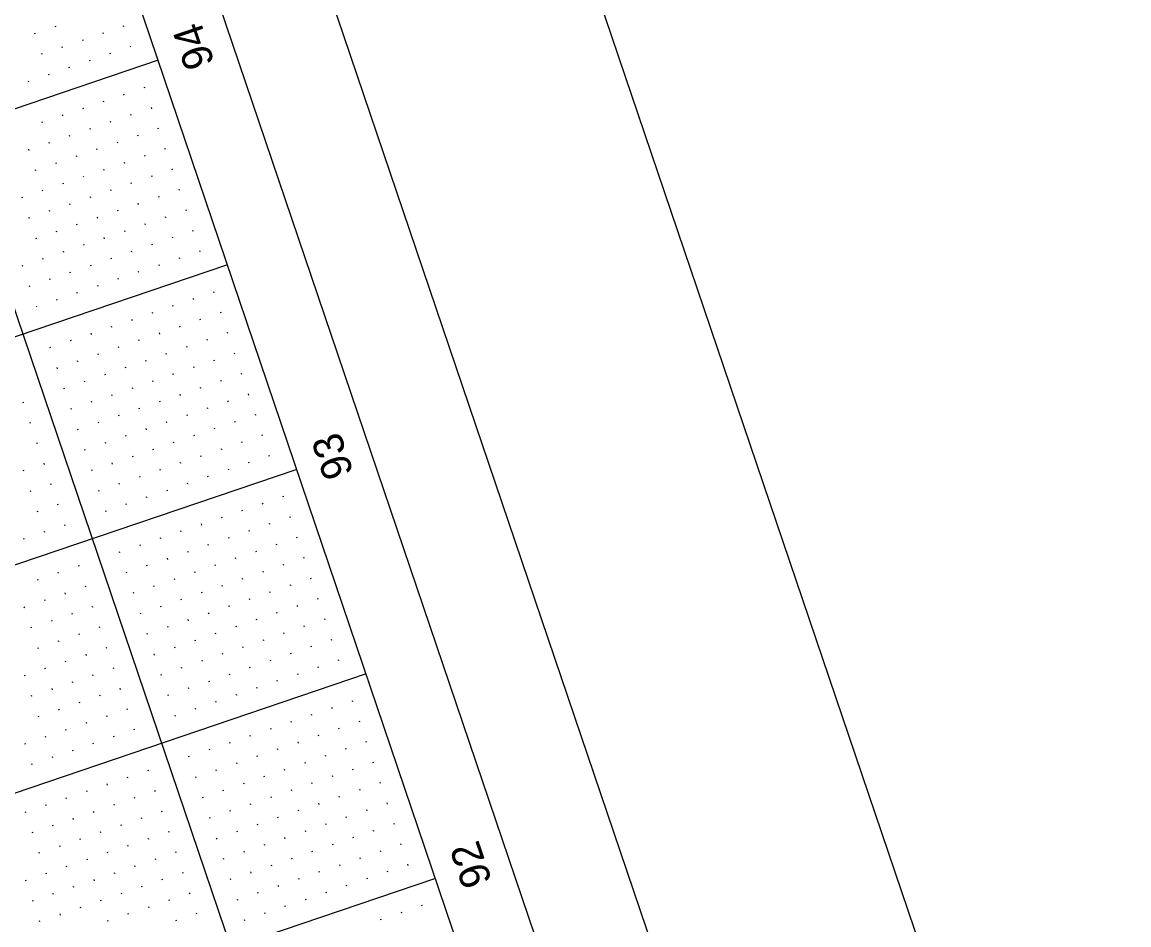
# Model space of a CAD drawing. Extents: x 2150318 to 2152065, y 143281 to 145371.
# Drawn here: x 2151643.3 to 2151899.7, y 144207 to 144416 of the extents above; entities that cross this region are included whole.
import ezdxf

# ---------------------------------------------------------------- set-up
doc = ezdxf.new("R2010")
doc.units = 0
for name, color, linetype in [('SHT_Plan_Profile_Sheet_Sta_Txt', 7, 'Continuous'), ('SHT_Plot_Shape_Full', 7, 'Continuous'), ('SHT_Plot_Shape_Half', 7, 'Continuous'), ('SHT_Profile_Grid_Major', 7, 'Continuous'), ('SHT_Profile_Grid_Minor', 7, 'Continuous'), ('SHT_Sheet_Border', 7, 'Continuous')]:
    doc.layers.add(name, color=color, linetype=linetype)

msp = doc.modelspace()

# ---------------------------------------------------------------- linework, layer by layer
at = {"layer": 'SHT_Plot_Shape_Full'}
msp.add_lwpolyline([(2150896.74, 143280.62), (2150318.46, 144985.2), (2151454.85, 145370.71), (2152033.12, 143666.13)], close=True, dxfattribs=at)
at = {"layer": 'SHT_Plot_Shape_Half'}
msp.add_lwpolyline([(2150909.49, 143371.4), (2150363.35, 144981.29), (2151405.04, 145334.68), (2151951.18, 143724.79)], close=True, dxfattribs=at)
at = {"layer": 'SHT_Profile_Grid_Major'}
for p, q in [((2151832.26, 143787.41), (2151326.27, 145278.92)), ((2151674.81, 144407.18), (2151224.91, 144254.55)), ((2151690.87, 144359.83), (2151240.97, 144207.2)), ((2151706.93, 144312.48), (2151257.04, 144159.85)), ((2151723, 144265.13), (2151273.1, 144112.5)), ((2151739.06, 144217.78), (2151308.18, 144071.6))]:
    msp.add_line(p, q, dxfattribs=at)
at = {"layer": 'SHT_Profile_Grid_Minor'}
for p, q in [((2151646.35, 144413.23), (2151646.27, 144413.47)), ((2151651.09, 144414.84), (2151651.01, 144415.07)), ((2151662.17, 144413.32), (2151662.09, 144413.55)), ((2151666.9, 144414.92), (2151666.82, 144415.16)), ((2151657.43, 144411.71), (2151657.35, 144411.95)), ((2151668.51, 144410.19), (2151668.43, 144410.42)), ((2151647.96, 144408.5), (2151647.88, 144408.73)), ((2151652.7, 144410.1), (2151652.62, 144410.34)), ((2151663.77, 144408.58), (2151663.69, 144408.82)), ((2151654.3, 144405.37), (2151654.22, 144405.6)), ((2151659.04, 144406.97), (2151658.96, 144407.21)), ((2151649.57, 144403.76), (2151649.49, 144404)), ((2151644.83, 144402.16), (2151644.75, 144402.39)), ((2151671.72, 144400.72), (2151671.64, 144400.95)), ((2151662.25, 144397.5), (2151662.17, 144397.74)), ((2151666.98, 144399.11), (2151666.9, 144399.35)), ((2151657.52, 144395.9), (2151657.43, 144396.13)), ((2151673.33, 144395.98), (2151673.25, 144396.22)), ((2151648.05, 144392.69), (2151647.96, 144392.92)), ((2151652.78, 144394.29), (2151652.7, 144394.53)), ((2151663.86, 144392.77), (2151663.78, 144393.01)), ((2151668.59, 144394.38), (2151668.51, 144394.61)), ((2151659.12, 144391.16), (2151659.04, 144391.4)), ((2151670.2, 144389.64), (2151670.12, 144389.88)), ((2151674.93, 144391.25), (2151674.85, 144391.48)), ((2151649.65, 144387.95), (2151649.57, 144388.19)), ((2151654.39, 144389.56), (2151654.31, 144389.79)), ((2151665.46, 144388.03), (2151665.38, 144388.27)), ((2151644.92, 144386.34), (2151644.84, 144386.58)), ((2151655.99, 144384.82), (2151655.91, 144385.06)), ((2151660.73, 144386.43), (2151660.65, 144386.66)), ((2151671.8, 144384.91), (2151671.72, 144385.14)), ((2151676.54, 144386.51), (2151676.46, 144386.75)), ((2151651.26, 144383.22), (2151651.18, 144383.45)), ((2151667.07, 144383.3), (2151666.99, 144383.54)), ((2151646.52, 144381.61), (2151646.44, 144381.85)), ((2151657.6, 144380.09), (2151657.52, 144380.32)), ((2151662.33, 144381.69), (2151662.25, 144381.93)), ((2151673.41, 144380.17), (2151673.33, 144380.41)), ((2151678.15, 144381.78), (2151678.06, 144382.01)), ((2151648.13, 144376.87), (2151648.05, 144377.11)), ((2151652.86, 144378.48), (2151652.78, 144378.72)), ((2151663.94, 144376.96), (2151663.86, 144377.19)), ((2151668.68, 144378.56), (2151668.59, 144378.8)), ((2151679.75, 144377.04), (2151679.67, 144377.28)), ((2151643.39, 144375.27), (2151643.31, 144375.5)), ((2151659.21, 144375.35), (2151659.13, 144375.59)), ((2151675.02, 144375.44), (2151674.94, 144375.67)), ((2151649.74, 144372.14), (2151649.66, 144372.38)), ((2151654.47, 144373.75), (2151654.39, 144373.98)), ((2151665.55, 144372.22), (2151665.47, 144372.46)), ((2151670.28, 144373.83), (2151670.2, 144374.07)), ((2151681.36, 144372.31), (2151681.28, 144372.54)), ((2151645, 144370.53), (2151644.92, 144370.77)), ((2151660.81, 144370.62), (2151660.73, 144370.85)), ((2151671.89, 144369.09), (2151671.81, 144369.33)), ((2151676.62, 144370.7), (2151676.54, 144370.94)), ((2151651.34, 144367.4), (2151651.26, 144367.64)), ((2151656.08, 144369.01), (2151656, 144369.25)), ((2151667.15, 144367.49), (2151667.07, 144367.72)), ((2151682.96, 144367.57), (2151682.88, 144367.81)), ((2151646.61, 144365.8), (2151646.53, 144366.03)), ((2151657.68, 144364.28), (2151657.6, 144364.51)), ((2151662.42, 144365.88), (2151662.34, 144366.12)), ((2151673.49, 144364.36), (2151673.41, 144364.6)), ((2151678.23, 144365.97), (2151678.15, 144366.2)), ((2151652.95, 144362.67), (2151652.87, 144362.91)), ((2151668.76, 144362.75), (2151668.68, 144362.99)), ((2151684.57, 144362.84), (2151684.49, 144363.07)), ((2151643.48, 144359.46), (2151643.4, 144359.69)), ((2151648.21, 144361.06), (2151648.13, 144361.3)), ((2151659.29, 144359.54), (2151659.21, 144359.78)), ((2151664.02, 144361.15), (2151663.94, 144361.38)), ((2151675.1, 144359.62), (2151675.02, 144359.86)), ((2151679.84, 144361.23), (2151679.76, 144361.47)), ((2151649.82, 144356.33), (2151649.74, 144356.56)), ((2151654.55, 144357.93), (2151654.47, 144358.17)), ((2151665.63, 144356.41), (2151665.55, 144356.65)), ((2151670.37, 144358.02), (2151670.29, 144358.26)), ((2151645.08, 144354.72), (2151645, 144354.96)), ((2151660.9, 144354.81), (2151660.82, 144355.04)), ((2151651.43, 144351.59), (2151651.35, 144351.83)), ((2151656.16, 144353.2), (2151656.08, 144353.44)), ((2151683.05, 144351.76), (2151682.97, 144352)), ((2151687.78, 144353.37), (2151687.7, 144353.6)), ((2151646.69, 144349.99), (2151646.61, 144350.22)), ((2151678.31, 144350.15), (2151678.23, 144350.39)), ((2151689.39, 144348.63), (2151689.31, 144348.87)), ((2151668.84, 144346.94), (2151668.76, 144347.18)), ((2151673.58, 144348.55), (2151673.5, 144348.79)), ((2151684.65, 144347.03), (2151684.57, 144347.26)), ((2151659.37, 144343.73), (2151659.29, 144343.97)), ((2151664.11, 144345.34), (2151664.03, 144345.57)), ((2151675.18, 144343.81), (2151675.1, 144344.05)), ((2151679.92, 144345.42), (2151679.84, 144345.66)), ((2151691, 144343.9), (2151690.92, 144344.13)), ((2151654.64, 144342.12), (2151654.56, 144342.36)), ((2151670.45, 144342.21), (2151670.37, 144342.44)), ((2151686.26, 144342.29), (2151686.18, 144342.53)), ((2151649.9, 144340.52), (2151649.82, 144340.75)), ((2151660.98, 144338.99), (2151660.9, 144339.23)), ((2151665.71, 144340.6), (2151665.63, 144340.84)), ((2151676.79, 144339.08), (2151676.71, 144339.32)), ((2151681.53, 144340.68), (2151681.45, 144340.92)), ((2151692.6, 144339.16), (2151692.52, 144339.4)), ((2151651.51, 144335.78), (2151651.43, 144336.02)), ((2151656.24, 144337.39), (2151656.16, 144337.62)), ((2151667.32, 144335.87), (2151667.24, 144336.1)), ((2151672.06, 144337.47), (2151671.98, 144337.71)), ((2151683.13, 144335.95), (2151683.05, 144336.19)), ((2151687.87, 144337.56), (2151687.79, 144337.79)), ((2151662.59, 144334.26), (2151662.51, 144334.5)), ((2151678.4, 144334.34), (2151678.32, 144334.58)), ((2151694.21, 144334.43), (2151694.13, 144334.66)), ((2151653.12, 144331.05), (2151653.04, 144331.28)), ((2151657.85, 144332.65), (2151657.77, 144332.89)), ((2151668.93, 144331.13), (2151668.85, 144331.37)), ((2151673.66, 144332.74), (2151673.58, 144332.97)), ((2151684.74, 144331.21), (2151684.66, 144331.45)), ((2151689.47, 144332.82), (2151689.39, 144333.06)), ((2151664.19, 144329.52), (2151664.11, 144329.76)), ((2151680, 144329.61), (2151679.92, 144329.85)), ((2151691.08, 144328.09), (2151691, 144328.32)), ((2151695.81, 144329.69), (2151695.73, 144329.93)), ((2151643.65, 144327.83), (2151643.57, 144328.07)), ((2151654.72, 144326.31), (2151654.64, 144326.55)), ((2151659.46, 144327.92), (2151659.38, 144328.16)), ((2151670.53, 144326.4), (2151670.45, 144326.63)), ((2151675.27, 144328), (2151675.19, 144328.24)), ((2151686.34, 144326.48), (2151686.26, 144326.72)), ((2151645.25, 144323.1), (2151645.17, 144323.34)), ((2151661.06, 144323.18), (2151660.98, 144323.42)), ((2151665.8, 144324.79), (2151665.72, 144325.03)), ((2151676.87, 144323.27), (2151676.79, 144323.5)), ((2151681.61, 144324.87), (2151681.53, 144325.11)), ((2151692.69, 144323.35), (2151692.61, 144323.59)), ((2151697.42, 144324.96), (2151697.34, 144325.19)), ((2151656.33, 144321.58), (2151656.25, 144321.81)), ((2151672.14, 144321.66), (2151672.06, 144321.9)), ((2151687.95, 144321.75), (2151687.87, 144321.98)), ((2151646.86, 144318.36), (2151646.78, 144318.6)), ((2151662.67, 144318.45), (2151662.59, 144318.69)), ((2151667.4, 144320.05), (2151667.32, 144320.29)), ((2151678.48, 144318.53), (2151678.4, 144318.77)), ((2151683.22, 144320.14), (2151683.14, 144320.38)), ((2151694.29, 144318.62), (2151694.21, 144318.85)), ((2151699.03, 144320.22), (2151698.95, 144320.46)), ((2151657.94, 144316.84), (2151657.85, 144317.08)), ((2151669.01, 144315.32), (2151668.93, 144315.56)), ((2151673.75, 144316.93), (2151673.67, 144317.16)), ((2151684.82, 144315.4), (2151684.74, 144315.64)), ((2151689.56, 144317.01), (2151689.48, 144317.25)), ((2151700.63, 144315.49), (2151700.55, 144315.72)), ((2151648.47, 144313.63), (2151648.38, 144313.87)), ((2151664.28, 144313.71), (2151664.2, 144313.95)), ((2151680.09, 144313.8), (2151680.01, 144314.03)), ((2151695.9, 144313.88), (2151695.82, 144314.12)), ((2151643.73, 144312.02), (2151643.65, 144312.26)), ((2151659.54, 144312.11), (2151659.46, 144312.34)), ((2151670.62, 144310.58), (2151670.54, 144310.82)), ((2151675.35, 144312.19), (2151675.27, 144312.43)), ((2151686.43, 144310.67), (2151686.35, 144310.91)), ((2151691.16, 144312.28), (2151691.08, 144312.51)), ((2151650.07, 144308.89), (2151649.99, 144309.13)), ((2151665.88, 144308.98), (2151665.8, 144309.22)), ((2151681.69, 144309.06), (2151681.61, 144309.3)), ((2151645.34, 144307.29), (2151645.26, 144307.52)), ((2151661.15, 144307.37), (2151661.07, 144307.61)), ((2151672.22, 144305.85), (2151672.14, 144306.09)), ((2151676.96, 144307.46), (2151676.88, 144307.69)), ((2151703.85, 144306.02), (2151703.77, 144306.25)), ((2151646.94, 144302.55), (2151646.86, 144302.79)), ((2151651.68, 144304.16), (2151651.6, 144304.4)), ((2151662.75, 144302.64), (2151662.67, 144302.87)), ((2151667.49, 144304.24), (2151667.41, 144304.48)), ((2151694.38, 144302.81), (2151694.3, 144303.04)), ((2151699.11, 144304.41), (2151699.03, 144304.65)), ((2151689.64, 144301.2), (2151689.56, 144301.44)), ((2151705.45, 144301.28), (2151705.37, 144301.52)), ((2151648.55, 144297.82), (2151648.47, 144298.06)), ((2151653.28, 144299.42), (2151653.2, 144299.66)), ((2151680.17, 144297.99), (2151680.09, 144298.22)), ((2151684.91, 144299.59), (2151684.83, 144299.83)), ((2151695.98, 144298.07), (2151695.9, 144298.31)), ((2151700.72, 144299.68), (2151700.64, 144299.91)), ((2151643.81, 144296.21), (2151643.73, 144296.45)), ((2151670.7, 144294.77), (2151670.62, 144295.01)), ((2151675.44, 144296.38), (2151675.36, 144296.62)), ((2151686.51, 144294.86), (2151686.43, 144295.09)), ((2151691.25, 144296.46), (2151691.17, 144296.7)), ((2151702.32, 144294.94), (2151702.24, 144295.18)), ((2151707.06, 144296.55), (2151706.98, 144296.78)), ((2151665.97, 144293.17), (2151665.89, 144293.4)), ((2151681.78, 144293.25), (2151681.7, 144293.49)), ((2151697.59, 144293.34), (2151697.51, 144293.57)), ((2151656.5, 144289.95), (2151656.42, 144290.19)), ((2151672.31, 144290.04), (2151672.23, 144290.28)), ((2151677.04, 144291.64), (2151676.96, 144291.88)), ((2151688.12, 144290.12), (2151688.04, 144290.36)), ((2151692.85, 144291.73), (2151692.77, 144291.97)), ((2151703.93, 144290.21), (2151703.85, 144290.44)), ((2151708.67, 144291.81), (2151708.58, 144292.05)), ((2151651.76, 144288.35), (2151651.68, 144288.59)), ((2151667.57, 144288.43), (2151667.49, 144288.67)), ((2151683.38, 144288.52), (2151683.3, 144288.75)), ((2151699.2, 144288.6), (2151699.11, 144288.84)), ((2151710.27, 144287.08), (2151710.19, 144287.31)), ((2151647.03, 144286.74), (2151646.95, 144286.98)), ((2151658.1, 144285.22), (2151658.02, 144285.46)), ((2151673.91, 144285.3), (2151673.83, 144285.54)), ((2151678.65, 144286.91), (2151678.57, 144287.15)), ((2151689.73, 144285.39), (2151689.65, 144285.62)), ((2151694.46, 144286.99), (2151694.38, 144287.23)), ((2151705.54, 144285.47), (2151705.46, 144285.71)), ((2151648.63, 144282.01), (2151648.55, 144282.24)), ((2151653.37, 144283.61), (2151653.29, 144283.85)), ((2151669.18, 144283.7), (2151669.1, 144283.93)), ((2151680.26, 144282.18), (2151680.18, 144282.41)), ((2151684.99, 144283.78), (2151684.91, 144284.02)), ((2151696.07, 144282.26), (2151695.99, 144282.5)), ((2151700.8, 144283.87), (2151700.72, 144284.1)), ((2151711.88, 144282.34), (2151711.8, 144282.58)), ((2151643.9, 144280.4), (2151643.82, 144280.64)), ((2151659.71, 144280.48), (2151659.63, 144280.72)), ((2151675.52, 144280.57), (2151675.44, 144280.81)), ((2151691.33, 144280.65), (2151691.25, 144280.89)), ((2151707.14, 144280.74), (2151707.06, 144280.97)), ((2151650.24, 144277.27), (2151650.16, 144277.51)), ((2151654.97, 144278.88), (2151654.89, 144279.12)), ((2151670.79, 144278.96), (2151670.71, 144279.2)), ((2151681.86, 144277.44), (2151681.78, 144277.68)), ((2151686.6, 144279.05), (2151686.52, 144279.28)), ((2151697.67, 144277.52), (2151697.59, 144277.76)), ((2151702.41, 144279.13), (2151702.33, 144279.37)), ((2151713.48, 144277.61), (2151713.4, 144277.84)), ((2151645.5, 144275.67), (2151645.42, 144275.9)), ((2151661.32, 144275.75), (2151661.24, 144275.99)), ((2151677.13, 144275.83), (2151677.05, 144276.07)), ((2151688.2, 144274.31), (2151688.12, 144274.55)), ((2151692.94, 144275.92), (2151692.86, 144276.15)), ((2151704.01, 144274.4), (2151703.93, 144274.63)), ((2151708.75, 144276), (2151708.67, 144276.24)), ((2151651.85, 144272.54), (2151651.77, 144272.77)), ((2151656.58, 144274.14), (2151656.5, 144274.38)), ((2151672.39, 144274.23), (2151672.31, 144274.46)), ((2151683.47, 144272.71), (2151683.39, 144272.94)), ((2151699.28, 144272.79), (2151699.2, 144273.03)), ((2151715.09, 144272.87), (2151715.01, 144273.11)), ((2151647.11, 144270.93), (2151647.03, 144271.17)), ((2151658.19, 144269.41), (2151658.11, 144269.65)), ((2151662.92, 144271.01), (2151662.84, 144271.25)), ((2151674, 144269.49), (2151673.92, 144269.73)), ((2151678.73, 144271.1), (2151678.65, 144271.34)), ((2151689.81, 144269.58), (2151689.73, 144269.81)), ((2151694.54, 144271.18), (2151694.46, 144271.42)), ((2151705.62, 144269.66), (2151705.54, 144269.9)), ((2151710.36, 144271.27), (2151710.28, 144271.5)), ((2151653.45, 144267.8), (2151653.37, 144268.04)), ((2151685.07, 144267.97), (2151684.99, 144268.21)), ((2151700.89, 144268.05), (2151700.81, 144268.29)), ((2151716.7, 144268.14), (2151716.62, 144268.37)), ((2151643.98, 144264.59), (2151643.9, 144264.83)), ((2151648.72, 144266.2), (2151648.64, 144266.43)), ((2151659.79, 144264.67), (2151659.71, 144264.91)), ((2151664.53, 144266.28), (2151664.45, 144266.52)), ((2151675.6, 144264.76), (2151675.52, 144264.99)), ((2151680.34, 144266.36), (2151680.26, 144266.6)), ((2151691.42, 144264.84), (2151691.34, 144265.08)), ((2151696.15, 144266.45), (2151696.07, 144266.68)), ((2151707.23, 144264.93), (2151707.15, 144265.16)), ((2151711.96, 144266.53), (2151711.88, 144266.77)), ((2151650.32, 144261.46), (2151650.24, 144261.7)), ((2151655.06, 144263.07), (2151654.98, 144263.3)), ((2151666.13, 144261.54), (2151666.05, 144261.78)), ((2151681.95, 144261.63), (2151681.87, 144261.87)), ((2151686.68, 144263.24), (2151686.6, 144263.47)), ((2151697.76, 144261.71), (2151697.68, 144261.95)), ((2151702.49, 144263.32), (2151702.41, 144263.56)), ((2151645.59, 144259.85), (2151645.51, 144260.09)), ((2151661.4, 144259.94), (2151661.32, 144260.18)), ((2151677.21, 144260.02), (2151677.13, 144260.26)), ((2151693.02, 144260.11), (2151692.94, 144260.34)), ((2151651.93, 144256.73), (2151651.85, 144256.96)), ((2151656.66, 144258.33), (2151656.58, 144258.57)), ((2151667.74, 144256.81), (2151667.66, 144257.05)), ((2151683.55, 144256.89), (2151683.47, 144257.13)), ((2151688.29, 144258.5), (2151688.21, 144258.74)), ((2151715.17, 144257.06), (2151715.09, 144257.3)), ((2151719.91, 144258.67), (2151719.83, 144258.91)), ((2151647.19, 144255.12), (2151647.11, 144255.36)), ((2151663.01, 144255.2), (2151662.93, 144255.44)), ((2151678.82, 144255.29), (2151678.74, 144255.52)), ((2151705.7, 144253.85), (2151705.62, 144254.09)), ((2151710.44, 144255.46), (2151710.36, 144255.69)), ((2151721.52, 144253.93), (2151721.44, 144254.17)), ((2151653.54, 144251.99), (2151653.46, 144252.23)), ((2151658.27, 144253.6), (2151658.19, 144253.83)), ((2151669.35, 144252.08), (2151669.27, 144252.31)), ((2151700.97, 144252.24), (2151700.89, 144252.48)), ((2151716.78, 144252.33), (2151716.7, 144252.56)), ((2151644.07, 144248.78), (2151643.99, 144249.02)), ((2151648.8, 144250.38), (2151648.72, 144250.62)), ((2151659.88, 144248.86), (2151659.8, 144249.1)), ((2151664.61, 144250.47), (2151664.53, 144250.71)), ((2151691.5, 144249.03), (2151691.42, 144249.27)), ((2151696.23, 144250.64), (2151696.15, 144250.87)), ((2151707.31, 144249.11), (2151707.23, 144249.35)), ((2151712.05, 144250.72), (2151711.97, 144250.96)), ((2151723.12, 144249.2), (2151723.04, 144249.44)), ((2151655.14, 144247.26), (2151655.06, 144247.49)), ((2151686.76, 144247.42), (2151686.68, 144247.66)), ((2151702.58, 144247.51), (2151702.5, 144247.74)), ((2151718.39, 144247.59), (2151718.31, 144247.83)), ((2151645.67, 144244.04), (2151645.59, 144244.28)), ((2151650.41, 144245.65), (2151650.33, 144245.89)), ((2151682.03, 144245.82), (2151681.95, 144246.05)), ((2151693.11, 144244.3), (2151693.03, 144244.53)), ((2151697.84, 144245.9), (2151697.76, 144246.14)), ((2151708.92, 144244.38), (2151708.84, 144244.62)), ((2151713.65, 144245.99), (2151713.57, 144246.22)), ((2151724.73, 144244.46), (2151724.65, 144244.7)), ((2151667.82, 144241), (2151667.74, 144241.24)), ((2151672.56, 144242.61), (2151672.48, 144242.84)), ((2151683.64, 144241.08), (2151683.56, 144241.32)), ((2151688.37, 144242.69), (2151688.29, 144242.93)), ((2151699.45, 144241.17), (2151699.37, 144241.4)), ((2151704.18, 144242.77), (2151704.1, 144243.01)), ((2151715.26, 144241.25), (2151715.18, 144241.49)), ((2151719.99, 144242.86), (2151719.91, 144243.09)), ((2151663.09, 144239.39), (2151663.01, 144239.63)), ((2151694.71, 144239.56), (2151694.63, 144239.8)), ((2151710.52, 144239.64), (2151710.44, 144239.88)), ((2151726.33, 144239.73), (2151726.25, 144239.97)), ((2151653.62, 144236.18), (2151653.54, 144236.42)), ((2151658.36, 144237.79), (2151658.27, 144238.02)), ((2151669.43, 144236.26), (2151669.35, 144236.5)), ((2151674.17, 144237.87), (2151674.09, 144238.11)), ((2151685.24, 144236.35), (2151685.16, 144236.58)), ((2151689.98, 144237.95), (2151689.9, 144238.19)), ((2151701.05, 144236.43), (2151700.97, 144236.67)), ((2151705.79, 144238.04), (2151705.71, 144238.27)), ((2151716.86, 144236.52), (2151716.78, 144236.75)), ((2151721.6, 144238.12), (2151721.52, 144238.36)), ((2151648.89, 144234.57), (2151648.8, 144234.81)), ((2151664.7, 144234.66), (2151664.62, 144234.89)), ((2151691.58, 144233.22), (2151691.5, 144233.46)), ((2151696.32, 144234.83), (2151696.24, 144235.06)), ((2151707.39, 144233.3), (2151707.31, 144233.54)), ((2151712.13, 144234.91), (2151712.05, 144235.15)), ((2151723.21, 144233.39), (2151723.13, 144233.62)), ((2151727.94, 144234.99), (2151727.86, 144235.23)), ((2151644.15, 144232.97), (2151644.07, 144233.2)), ((2151655.23, 144231.44), (2151655.15, 144231.68)), ((2151659.96, 144233.05), (2151659.88, 144233.29)), ((2151671.04, 144231.53), (2151670.96, 144231.77)), ((2151675.77, 144233.14), (2151675.69, 144233.37)), ((2151686.85, 144231.61), (2151686.77, 144231.85)), ((2151702.66, 144231.7), (2151702.58, 144231.93)), ((2151718.47, 144231.78), (2151718.39, 144232.02)), ((2151645.76, 144228.23), (2151645.68, 144228.47)), ((2151650.49, 144229.84), (2151650.41, 144230.08)), ((2151661.57, 144228.32), (2151661.49, 144228.55)), ((2151666.3, 144229.92), (2151666.22, 144230.16)), ((2151677.38, 144228.4), (2151677.3, 144228.64)), ((2151693.19, 144228.48), (2151693.11, 144228.72)), ((2151697.92, 144230.09), (2151697.84, 144230.33)), ((2151709, 144228.57), (2151708.92, 144228.81)), ((2151713.74, 144230.17), (2151713.66, 144230.41)), ((2151724.81, 144228.65), (2151724.73, 144228.89)), ((2151729.55, 144230.26), (2151729.47, 144230.5)), ((2151656.83, 144226.71), (2151656.75, 144226.95)), ((2151672.64, 144226.79), (2151672.56, 144227.03)), ((2151688.46, 144226.88), (2151688.37, 144227.11)), ((2151704.27, 144226.96), (2151704.19, 144227.2)), ((2151720.08, 144227.05), (2151720, 144227.28)), ((2151731.15, 144225.52), (2151731.07, 144225.76)), ((2151647.36, 144223.5), (2151647.28, 144223.73)), ((2151652.1, 144225.1), (2151652.02, 144225.34)), ((2151663.17, 144223.58), (2151663.09, 144223.82)), ((2151667.91, 144225.19), (2151667.83, 144225.42)), ((2151678.99, 144223.67), (2151678.9, 144223.9)), ((2151694.8, 144223.75), (2151694.72, 144223.99)), ((2151699.53, 144225.36), (2151699.45, 144225.59)), ((2151710.61, 144223.83), (2151710.53, 144224.07)), ((2151715.34, 144225.44), (2151715.26, 144225.68)), ((2151726.42, 144223.92), (2151726.34, 144224.15)), ((2151658.44, 144221.98), (2151658.36, 144222.21)), ((2151669.52, 144220.45), (2151669.43, 144220.69)), ((2151674.25, 144222.06), (2151674.17, 144222.3)), ((2151690.06, 144222.14), (2151689.98, 144222.38)), ((2151701.14, 144220.62), (2151701.06, 144220.86)), ((2151705.87, 144222.23), (2151705.79, 144222.46)), ((2151716.95, 144220.7), (2151716.87, 144220.94)), ((2151721.68, 144222.31), (2151721.6, 144222.55)), ((2151732.76, 144220.79), (2151732.68, 144221.03)), ((2151648.97, 144218.76), (2151648.89, 144219)), ((2151653.7, 144220.37), (2151653.62, 144220.61)), ((2151664.78, 144218.85), (2151664.7, 144219.08)), ((2151680.59, 144218.93), (2151680.51, 144219.17)), ((2151696.4, 144219.01), (2151696.32, 144219.25)), ((2151712.21, 144219.1), (2151712.13, 144219.34)), ((2151728.02, 144219.18), (2151727.94, 144219.42)), ((2151644.23, 144217.16), (2151644.15, 144217.39)), ((2151655.31, 144215.63), (2151655.23, 144215.87)), ((2151660.05, 144217.24), (2151659.96, 144217.48)), ((2151671.12, 144215.72), (2151671.04, 144215.95)), ((2151675.86, 144217.32), (2151675.78, 144217.56)), ((2151691.67, 144217.41), (2151691.59, 144217.64)), ((2151702.74, 144215.89), (2151702.66, 144216.12)), ((2151707.48, 144217.49), (2151707.4, 144217.73)), ((2151718.56, 144215.97), (2151718.47, 144216.21)), ((2151723.29, 144217.58), (2151723.21, 144217.81)), ((2151650.58, 144214.03), (2151650.5, 144214.26)), ((2151666.39, 144214.11), (2151666.31, 144214.35)), ((2151682.2, 144214.2), (2151682.12, 144214.43)), ((2151698.01, 144214.28), (2151697.93, 144214.52)), ((2151709.09, 144212.76), (2151709, 144212.99)), ((2151713.82, 144214.36), (2151713.74, 144214.6)), ((2151645.84, 144212.42), (2151645.76, 144212.66)), ((2151656.92, 144210.9), (2151656.84, 144211.14)), ((2151661.65, 144212.51), (2151661.57, 144212.74)), ((2151672.73, 144210.98), (2151672.65, 144211.22)), ((2151677.46, 144212.59), (2151677.38, 144212.83)), ((2151693.27, 144212.67), (2151693.19, 144212.91)), ((2151704.35, 144211.15), (2151704.27, 144211.39)), ((2151735.97, 144211.32), (2151735.89, 144211.56)), ((2151647.45, 144207.69), (2151647.37, 144207.92)), ((2151652.18, 144209.29), (2151652.1, 144209.53)), ((2151663.26, 144207.77), (2151663.18, 144208.01)), ((2151667.99, 144209.38), (2151667.91, 144209.61)), ((2151679.07, 144207.85), (2151678.99, 144208.09)), ((2151683.8, 144209.46), (2151683.72, 144209.7)), ((2151694.88, 144207.94), (2151694.8, 144208.17)), ((2151699.62, 144209.54), (2151699.53, 144209.78)), ((2151726.5, 144208.11), (2151726.42, 144208.34)), ((2151731.24, 144209.71), (2151731.16, 144209.95))]:
    msp.add_line(p, q, dxfattribs=at)
at = {"layer": 'SHT_Sheet_Border'}
msp.add_line((2151879.61, 143803.47), (2151457.96, 145046.39), dxfattribs=at)
msp.add_lwpolyline([(2150901.85, 143471.77), (2150395.86, 144963.28), (2151390.2, 145300.6), (2151896.19, 143809.09)], close=True, dxfattribs=at)

# ---------------------------------------------------------------- texts
at = {"layer": 'SHT_Plan_Profile_Sheet_Sta_Txt'}
for s, p in [('94', (2151687.97, 144406.51)), ('93', (2151720.16, 144311.63)), ('92', (2151752.24, 144217.06))]:
    msp.add_text(s, height=7, rotation=108.7393, dxfattribs=at).set_placement(p)

doc.saveas('drawing.dxf')
